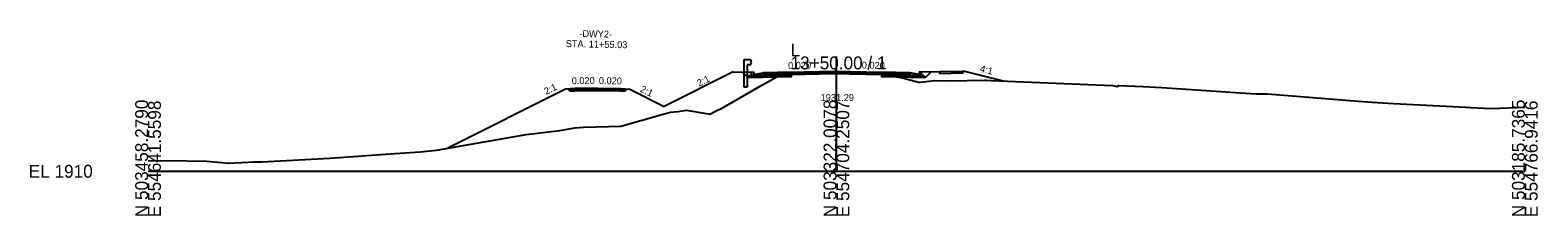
# Model space of a CAD drawing. Extents: x -26 to 4603, y -10 to 4703.
# Drawn here: x -25.7 to 302.8, y 1510.3 to 1550.7 of the extents above; entities that cross this region are included whole.
import ezdxf

# ---------------------------------------------------------------- set-up
doc = ezdxf.new("R2010")
doc.units = 0
for name, color, linetype in [('Default', 7, 'Continuous'), ('Exist Cross Section Cell', 7, 'Continuous'), ('Exist XS Ground Line', 7, 'Continuous'), ('Prop CMT Guardrail Graphics', 7, 'Continuous'), ('Prop CMT Pvmt Course 1', 7, 'Continuous'), ('Prop CMT Pvmt Course 2', 7, 'Continuous'), ('Prop CMT Pvmt Course 3', 7, 'Continuous'), ('Prop CMT Pvmt Milling', 7, 'Continuous'), ('Prop CMT Pvmt Surface', 7, 'Continuous'), ('Prop CMT Shear Line', 7, 'Continuous'), ('Prop CMT Shld Paved Course 1', 7, 'Continuous'), ('Prop CMT Shld Paved Course 2', 7, 'Continuous'), ('Prop CMT Shld Paved Course 3', 7, 'Continuous'), ('Prop CMT Slope Grass', 7, 'Continuous'), ('Prop CMT Subgrade Earthwork', 7, 'Continuous'), ('Prop Conc 4in Sidewalk', 7, 'Continuous'), ('Prop Conc Curb and Gutter', 7, 'Continuous'), ('Prop Corridor Mesh Bottom', 7, 'Continuous'), ('Prop XS Finish Grade', 7, 'Continuous'), ('Prop XS Label Text', 7, 'Continuous'), ('Prop XS SE Text', 7, 'Continuous'), ('Prop XS Side Slope Text', 7, 'Continuous'), ('Prop XS SS Elevation Text', 7, 'Continuous'), ('Scratch_Level_9', 7, 'Continuous')]:
    doc.layers.add(name, color=color, linetype=linetype)

msp = doc.modelspace()

# ---------------------------------------------------------------- linework, layer by layer
at = {"layer": 'Exist Cross Section Cell'}
for p, q in [((150, 1520), (150, 1545)), ((0, 1520), (150, 1520)), ((150, 1520), (300, 1520))]:
    msp.add_line(p, q, dxfattribs=at)
at = {"layer": 'Exist XS Ground Line'}
msp.add_lwpolyline([(0, 1522.3), (4.14, 1522.35), (12.79, 1522.21), (15.97, 1521.94), (17.36, 1521.75), (21.82, 1522), (22.87, 1522.06), (24.82, 1522.06), (39.61, 1522.89), (52.79, 1523.82), (59.26, 1524.23), (62.83, 1524.63), (82.4, 1528.01), (83.03, 1528.11), (89.7, 1528.92), (93.01, 1529.49), (94.86, 1529.59), (102.99, 1529.8), (112.76, 1532.56), (113.84, 1532.88), (115.45, 1533.04), (117.35, 1533.29), (121.16, 1532.64), (122.42, 1532.41), (123.52, 1532.99), (125.3, 1533.91), (133.72, 1538.74), (136.34, 1540.2), (137.09, 1540.66), (137.32, 1540.69), (140.19, 1541.1), (143.09, 1541.18), (149.5, 1541.29), (152.97, 1541.25), (159.85, 1541.16), (161.12, 1540.96), (164.41, 1540.36), (167.89, 1539.44), (167.91, 1539.44), (168.11, 1539.38), (168.22, 1539.39), (171.42, 1539.75), (174.55, 1539.72), (182.3, 1539.83), (182.76, 1539.82), (183.71, 1539.78), (210.15, 1538.66), (211.16, 1538.49), (211.51, 1538.67), (216.84, 1538.44), (220.93, 1538.27), (238.05, 1537.11), (241.45, 1536.85), (243.94, 1536.84), (263.72, 1535.28), (266.77, 1535.06), (271.37, 1534.78), (287.13, 1534), (288.17, 1533.87), (292.7, 1533.68), (300, 1533.96)], dxfattribs=at)
at = {"layer": 'Prop CMT Guardrail Graphics'}
for points in [[(129.89, 1538.35), (129.89, 1544.35)], [(129.89, 1544.35), (131.23, 1544.35), (131.5, 1544.06)], [(131.5, 1543.47), (131.23, 1543.18), (130.56, 1543.18)], [(130.56, 1543.18), (130.56, 1538.35)], [(131.5, 1544.06), (131.23, 1543.77)], [(131.23, 1543.77), (131.5, 1543.47)], [(130.56, 1538.35), (129.89, 1538.35)]]:
    msp.add_lwpolyline(points, dxfattribs=at)
at = {"layer": 'Prop CMT Pvmt Course 1'}
for points in [[(140.19, 1541.59), (134, 1541.47), (134, 1541.22), (134, 1541.22), (140.19, 1541.34), (140.19, 1541.34), (140.19, 1541.34), (140.19, 1541.59), (140.19, 1541.59)], [(150, 1541.79), (150, 1541.79), (150, 1541.29), (150, 1541.29), (150, 1541.29), (149.5, 1541.29), (149.5, 1541.29), (143.09, 1541.18), (143.09, 1541.18), (140.19, 1541.1), (140.19, 1541.1), (140.19, 1541.59), (143.09, 1541.65), (143.09, 1541.65), (149.5, 1541.78), (149.5, 1541.78), (150, 1541.79)], [(159.85, 1541.59), (159.85, 1541.16), (159.85, 1541.16), (152.97, 1541.25), (152.97, 1541.25), (150, 1541.29), (150, 1541.29), (150, 1541.79), (152.97, 1541.73), (152.97, 1541.73), (159.85, 1541.59)], [(166, 1541.47), (159.85, 1541.59), (159.85, 1541.34), (159.85, 1541.34), (166, 1541.22), (166, 1541.22), (166, 1541.22), (166, 1541.47), (166, 1541.47)], [(97.96, 1538.13), (92.96, 1538.03)], [(92.96, 1538.03), (92.96, 1537.78)], [(92.96, 1537.78), (97.96, 1537.88)], [(97.96, 1537.88), (97.96, 1538.13)], [(97.96, 1538.13), (102.96, 1538.03)], [(97.96, 1537.88), (97.96, 1538.13)], [(102.96, 1537.78), (97.96, 1537.88)], [(102.96, 1538.03), (102.96, 1537.78)]]:
    msp.add_lwpolyline(points, dxfattribs=at)
msp.add_lwpolyline([(97.96, 1537.88), (97.96, 1538.01), (97.96, 1538.01), (97.96, 1537.88)], close=True, dxfattribs=at)
msp.add_lwpolyline([(97.96, 1537.88), (97.96, 1538.01), (97.96, 1538.01), (97.96, 1537.88)], close=True, dxfattribs=at)
at = {"layer": 'Prop CMT Pvmt Course 2'}
for points in [[(140.19, 1541.34), (134, 1541.22), (134, 1540.89), (134, 1540.89), (140.19, 1541.01), (140.19, 1541.01), (140.19, 1541.01), (140.19, 1541.34), (140.19, 1541.34)], [(166, 1541.22), (159.85, 1541.34), (159.85, 1541.01), (159.85, 1541.01), (166, 1540.89), (166, 1540.89), (166, 1540.89), (166, 1541.22), (166, 1541.22)], [(97.96, 1537.88), (92.96, 1537.78)], [(92.96, 1537.78), (92.96, 1537.53)], [(92.96, 1537.53), (97.96, 1537.63)], [(97.96, 1537.63), (97.96, 1537.88)], [(97.96, 1537.63), (97.96, 1537.88)], [(97.96, 1537.88), (102.96, 1537.78)], [(102.96, 1537.53), (97.96, 1537.63)], [(102.96, 1537.78), (102.96, 1537.53)]]:
    msp.add_lwpolyline(points, dxfattribs=at)
at = {"layer": 'Prop CMT Pvmt Course 3'}
for points in [[(140.19, 1541.01), (134, 1540.89), (134, 1540.51), (134, 1540.51), (140.19, 1540.63), (140.19, 1540.63), (140.19, 1540.63), (140.19, 1541.01), (140.19, 1541.01)], [(166, 1540.89), (159.85, 1541.01), (159.85, 1540.63), (159.85, 1540.63), (166, 1540.51), (166, 1540.51), (166, 1540.51), (166, 1540.89), (166, 1540.89)], [(169, 1540.83), (166, 1540.89), (166, 1540.51), (166, 1540.51), (169.38, 1540.44), (169.38, 1540.44), (169.38, 1540.44), (169, 1540.83), (169, 1540.83)]]:
    msp.add_lwpolyline(points, dxfattribs=at)
at = {"layer": 'Prop CMT Pvmt Milling'}
for points in [[(140.19, 1541.1), (143.09, 1541.18), (143.09, 1541.18), (149.5, 1541.29), (149.5, 1541.29), (150, 1541.29), (150, 1541.29)], [(159.85, 1541.16), (152.97, 1541.25), (152.97, 1541.25), (150, 1541.29)]]:
    msp.add_lwpolyline(points, dxfattribs=at)
at = {"layer": 'Prop CMT Pvmt Surface'}
for points in [[(97.96, 1538.13), (92.96, 1538.03)], [(97.96, 1538.13), (102.96, 1538.03)]]:
    msp.add_lwpolyline(points, dxfattribs=at)
at = {"layer": 'Prop CMT Shld Paved Course 1'}
for points in [[(92.96, 1538.03), (92.7, 1537.78)], [(92.7, 1537.78), (92.96, 1537.78)], [(92.96, 1537.78), (92.96, 1538.03)], [(102.96, 1538.03), (103.21, 1537.78)], [(102.96, 1537.78), (102.96, 1538.03)], [(103.21, 1537.78), (102.96, 1537.78)]]:
    msp.add_lwpolyline(points, dxfattribs=at)
at = {"layer": 'Prop CMT Shld Paved Course 2'}
for points in [[(150, 1541.54), (150, 1541.54), (150, 1541.21), (150, 1541.21), (150, 1541.21), (149.5, 1541.2), (149.5, 1541.2), (143.09, 1541.07), (143.09, 1541.07), (140.19, 1541.01), (140.19, 1541.01), (140.19, 1541.34), (143.09, 1541.4), (143.09, 1541.4), (149.5, 1541.53), (149.5, 1541.53), (150, 1541.54)], [(159.85, 1541.34), (159.85, 1541.01), (159.85, 1541.01), (152.97, 1541.15), (152.97, 1541.15), (150, 1541.21), (150, 1541.21), (150, 1541.54), (152.97, 1541.48), (152.97, 1541.48), (159.85, 1541.34)], [(92.96, 1537.78), (92.7, 1537.78), (92.2, 1537.77), (91.95, 1537.51)], [(92.96, 1537.53), (92.96, 1537.78)], [(102.96, 1537.78), (103.21, 1537.78), (103.71, 1537.77), (103.97, 1537.51)], [(102.96, 1537.53), (102.96, 1537.78)], [(91.95, 1537.51), (92.96, 1537.53)], [(103.97, 1537.51), (102.96, 1537.53)]]:
    msp.add_lwpolyline(points, dxfattribs=at)
at = {"layer": 'Prop CMT Shld Paved Course 3'}
msp.add_lwpolyline([(131, 1540.83), (134, 1540.89), (134, 1540.51), (134, 1540.51), (130.7, 1540.44), (130.7, 1540.44), (130.7, 1540.44), (131, 1540.83), (131, 1540.83)], dxfattribs=at)
at = {"layer": 'Prop CMT Slope Grass'}
for points in [[(92.96, 1538.03), (90.96, 1537.87), (65.34, 1525.07)], [(102.96, 1538.03), (104.96, 1537.87), (112.43, 1534.14)]]:
    msp.add_lwpolyline(points, dxfattribs=at)
at = {"layer": 'Prop CMT Subgrade Earthwork'}
for points in [[(129.54, 1541.61), (130.7, 1540.44), (130.7, 1540.44)], [(170.55, 1541.61), (169.38, 1540.44), (169.38, 1540.44)], [(92.96, 1537.53), (91.95, 1537.51), (91.54, 1537.92)], [(97.96, 1537.63), (92.96, 1537.53)], [(97.96, 1537.63), (102.96, 1537.53)], [(102.96, 1537.53), (103.97, 1537.51), (104.37, 1537.92)], [(130.7, 1540.44), (140.19, 1540.63), (140.19, 1540.63)], [(169.38, 1540.44), (169.38, 1540.44), (159.85, 1540.63)]]:
    msp.add_lwpolyline(points, dxfattribs=at)
at = {"layer": 'Prop Conc 4in Sidewalk'}
msp.add_lwpolyline([(172.5, 1541.65), (172.5, 1541.65), (172.49, 1541.32), (172.49, 1541.32), (172.49, 1541.32), (177.51, 1541.42), (177.51, 1541.42), (177.5, 1541.75), (172.5, 1541.65)], dxfattribs=at)
at = {"layer": 'Prop Conc Curb and Gutter'}
for points in [[(132, 1541.07), (134, 1541.47), (134, 1540.89), (134, 1540.89), (131.5, 1540.84), (131.5, 1540.84), (131.5, 1540.84), (131.5, 1541.57), (131.5, 1541.57), (132, 1541.57), (132, 1541.07), (132, 1541.07), (132, 1541.07)], [(168, 1541.07), (166, 1541.47), (166, 1540.89), (166, 1540.89), (168.5, 1540.84), (168.5, 1540.84), (168.5, 1540.84), (168.5, 1541.57), (168.5, 1541.57), (168, 1541.57), (168, 1541.07), (168, 1541.07), (168, 1541.07)]]:
    msp.add_lwpolyline(points, dxfattribs=at)
at = {"layer": 'Prop Corridor Mesh Bottom'}
msp.add_lwpolyline([(166, 1541.47), (166, 1541.22)], dxfattribs=at)
at = {"layer": 'Prop XS Finish Grade'}
msp.add_line((127.5, 1541.65), (112.43, 1534.14), dxfattribs=at)
for points in [[(127.5, 1541.65), (131.5, 1541.57), (131.5, 1541.57)], [(172.5, 1541.65), (168.5, 1541.57), (168.5, 1541.57)], [(178, 1541.76), (177.5, 1541.75), (177.5, 1541.75)], [(186.38, 1539.66), (186.38, 1539.66), (178, 1541.76)]]:
    msp.add_lwpolyline(points, dxfattribs=at)
at = {"layer": 'Scratch_Level_9'}
msp.add_lwpolyline([(134, 1541.47), (134, 1541.22)], dxfattribs=at)

# ---------------------------------------------------------------- texts
at = {"layer": 'Default'}
msp.add_text('-', height=0.0001, dxfattribs=at).set_placement((0, 1520))
at = {"layer": 'Exist Cross Section Cell'}
for s, p in [('L', (140, 1545)), ('13+50.00 / 1', (140, 1542.2)), ('EL 1910', (-26, 1518.6))]:
    msp.add_text(s, height=2.8, dxfattribs=at).set_placement(p)
for s, p in [('N 503458.2790', (0, 1510)), ('E 554641.5598', (2.8, 1510)), ('N 503322.0078', (150, 1510)), ('E 554704.2507', (152.8, 1510)), ('N 503185.7365', (300, 1510)), ('E 554766.9416', (302.8, 1510))]:
    msp.add_text(s, height=2.8, rotation=90, dxfattribs=at).set_placement(p)
at = {"layer": 'Prop CMT Shear Line'}
for p in [(132, 1541.07), (134, 1541.47), (134, 1541.47), (150, 1541.79), (166, 1541.47), (166, 1541.47), (168, 1541.07), (172.5, 1541.65), (177.5, 1541.75), (178, 1541.76), (186.38, 1539.66), (108.43, 1531.33), (108.43, 1531.33)]:
    msp.add_text('X', height=0.0025, dxfattribs=at).set_placement(p)
at = {"layer": 'Prop XS Label Text'}
for s, rotation, p in [('0.020', 1.1458, (139.48, 1542.28)), ('0.020', 358.8542, (155.51, 1542.38)), ('4:1', 345.9638, (181.17, 1541.69))]:
    msp.add_text(s, height=1.5, rotation=rotation, dxfattribs=at).set_placement(p)
at = {"layer": 'Prop XS SE Text'}
for s, rotation, p in [('-DWY2-', 358.8542, (93.96, 1549.25)), ('STA. 11+55.03', 358.8542, (91, 1547.06)), ('0.020', 1.1458, (92.33, 1538.95)), ('0.020', 358.8542, (98.22, 1539.01))]:
    msp.add_text(s, height=1.5, rotation=rotation, dxfattribs=at).set_placement(p)
at = {"layer": 'Prop XS Side Slope Text'}
for rotation, p in [(26.5651, (86.76, 1536.61)), (333.4349, (107.09, 1537.41)), (26.5651, (120.09, 1538.42))]:
    msp.add_text('2:1', height=1.5, rotation=rotation, dxfattribs=at).set_placement(p)
at = {"layer": 'Prop XS SS Elevation Text'}
msp.add_text('1931.29', height=1.5, dxfattribs=at).set_placement((146.57, 1535.31))

doc.saveas('drawing.dxf')
